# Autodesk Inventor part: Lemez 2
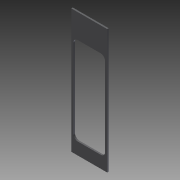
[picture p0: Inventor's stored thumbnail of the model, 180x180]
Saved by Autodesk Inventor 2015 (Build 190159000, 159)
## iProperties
Created: 2013-02
Part Number: Lemez 2
Material: Generic
Document SubType Name: Modeling
Designer: Marci
Density: 1 g/cm^3
Appearance: Gray
Author: Marci
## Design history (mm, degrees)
sketch "Sketch1"
  geometry: L1 (0, 0)-(0, 3.5); L2 (0, 3.5)-(82, 3.5); L3 (82, 3.5)-(82, 0); L4 (82, 0)-(0, 0)
  constraints: 8 end point, 2 parallel, 1 perpendicular, 1 vertical
  dimensions: "d0" = 3.5 distance of L1.start L1.end; "d1" = 82 distance of L1.end L2.end
extrude "Extrusion1" new body sketch "Sketch1" distance "d2" = 282.6; taper "d3" = 0 deg
sketch "Sketch2"
  geometry: L1 (0, 0)-(0, 282.6) reference; L2 (82, 0)-(0, 0) reference; L3 (82, 0)-(82, 282.6) reference; L4 (41, 227.6)-(67, 227.6); L5 (77, 217.6)-(77, 37.6); L6 (67, 27.6)-(15, 27.6); L7 (5, 37.6)-(5, 217.6); L8 (15, 227.6)-(41, 227.6); A1 r 10 centre (15, 217.6) between (15, 227.6) and (5, 217.6); A2 r 10 centre (67, 217.6) between (77, 217.6) and (67, 227.6); A3 r 10 centre (15, 37.6) between (5, 37.6) and (15, 27.6); A4 r 10 centre (67, 37.6) between (67, 27.6) and (77, 37.6); 3 further points
  constraints: 10 end point, 8 point on circle, 8 tangent, 6 point on line, 4 centre point, 3 equal radius, 3 perpendicular, 1 collinear, 1 parallel
  dimensions: "d5" = 36 distance of L4.start point (77, 227.6); "d6" = 200 distance of point (77, 227.6) point (77, 27.6); "d7" = 72 distance of point (77, 27.6) point (5, 27.6); "d8" = 10 radius of A1
extrude "Extrusion2" cut sketch "Sketch2" distance "d9" = 282.6; taper "d10" = 0 deg
body "Solid1"
